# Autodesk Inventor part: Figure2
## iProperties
Shininess: 77.0
Length Units: 11269
Angle Units: 11279
Time Units: 11290
Mass Units: 11283
Length Display Precision: 3
Angle Display Precision: 2
Created: 2001-12
Part Number: Figure2
Document SubType Name: Modeling
Designer: CADSoft
Density: 1 g/cm^3
Density: 0.0
Volumn: 0.0
Area: 0.0
PropertySet Name: Model Information
Control State: 0
Master: False
Checked Out: False
Author: CADSoft
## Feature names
1. Sweep7
